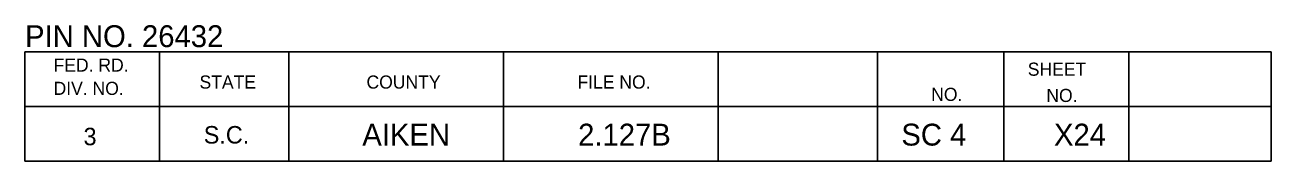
# Model space of a CAD drawing. Extents: x 1000 to 1162, y 999 to 8520.
# Drawn here: x 1133.06 to 1161.56, y 3745.05 to 3748.16 of the extents above; entities that cross this region are included whole.
import ezdxf

# ---------------------------------------------------------------- set-up
doc = ezdxf.new("R2010")
doc.units = 0
doc.layers.add('Level 20', color=7, linetype='Continuous')
doc.layers.add('Level 3', color=7, linetype='Continuous')

msp = doc.modelspace()

# ---------------------------------------------------------------- linework, layer by layer
at = {"layer": 'Level 3'}
for p, q in [((1133.055, 3747.546), (1161.555, 3747.546)), ((1133.055, 3747.546), (1133.055, 3745.046)), ((1133.055, 3747.546), (1161.555, 3747.546)), ((1133.055, 3747.546), (1133.055, 3745.046)), ((1133.055, 3747.546), (1161.555, 3747.546)), ((1133.055, 3747.546), (1133.055, 3745.046)), ((1133.055, 3747.546), (1161.555, 3747.546)), ((1133.055, 3747.546), (1133.055, 3745.046)), ((1133.055, 3747.546), (1161.555, 3747.546)), ((1133.055, 3747.546), (1133.055, 3745.046)), ((1133.055, 3747.546), (1161.555, 3747.546)), ((1133.055, 3747.546), (1133.055, 3745.046)), ((1133.055, 3747.546), (1161.555, 3747.546)), ((1133.055, 3747.546), (1133.055, 3745.046)), ((1133.055, 3747.546), (1161.555, 3747.546)), ((1133.055, 3747.546), (1133.055, 3745.046)), ((1133.055, 3747.546), (1161.555, 3747.546)), ((1133.055, 3747.546), (1133.055, 3745.046)), ((1133.055, 3747.546), (1161.555, 3747.546)), ((1133.055, 3747.546), (1133.055, 3745.046)), ((1133.055, 3747.546), (1161.555, 3747.546)), ((1133.055, 3747.546), (1133.055, 3745.046)), ((1133.055, 3747.546), (1161.555, 3747.546)), ((1133.055, 3747.546), (1133.055, 3745.046)), ((1133.055, 3747.546), (1161.555, 3747.546)), ((1133.055, 3747.546), (1133.055, 3745.046)), ((1133.055, 3747.546), (1161.555, 3747.546)), ((1133.055, 3747.546), (1133.055, 3745.046)), ((1133.055, 3747.546), (1161.555, 3747.546)), ((1133.055, 3747.546), (1133.055, 3745.046)), ((1133.055, 3747.546), (1161.555, 3747.546)), ((1133.055, 3747.546), (1133.055, 3745.046)), ((1133.055, 3747.546), (1161.555, 3747.546)), ((1133.055, 3747.546), (1133.055, 3745.046)), ((1133.055, 3747.546), (1161.555, 3747.546)), ((1133.055, 3747.546), (1133.055, 3745.046)), ((1133.055, 3747.546), (1161.555, 3747.546)), ((1133.055, 3747.546), (1133.055, 3745.046)), ((1133.055, 3747.546), (1161.555, 3747.546)), ((1133.055, 3747.546), (1133.055, 3745.046)), ((1133.055, 3747.546), (1161.555, 3747.546)), ((1133.055, 3747.546), (1133.055, 3745.046)), ((1133.055, 3747.546), (1161.555, 3747.546)), ((1133.055, 3747.546), (1133.055, 3745.046)), ((1136.132, 3747.546), (1136.132, 3745.046)), ((1136.132, 3747.546), (1136.132, 3745.046)), ((1136.132, 3747.546), (1136.132, 3745.046)), ((1136.132, 3747.546), (1136.132, 3745.046)), ((1136.132, 3747.546), (1136.132, 3745.046)), ((1136.132, 3747.546), (1136.132, 3745.046)), ((1136.132, 3747.546), (1136.132, 3745.046)), ((1136.132, 3747.546), (1136.132, 3745.046)), ((1136.132, 3747.546), (1136.132, 3745.046)), ((1136.132, 3747.546), (1136.132, 3745.046)), ((1136.132, 3747.546), (1136.132, 3745.046)), ((1136.132, 3747.546), (1136.132, 3745.046)), ((1136.132, 3747.546), (1136.132, 3745.046)), ((1136.132, 3747.546), (1136.132, 3745.046)), ((1136.132, 3747.546), (1136.132, 3745.046)), ((1136.132, 3747.546), (1136.132, 3745.046)), ((1136.132, 3747.546), (1136.132, 3745.046)), ((1136.132, 3747.546), (1136.132, 3745.046)), ((1136.132, 3747.546), (1136.132, 3745.046)), ((1136.132, 3747.546), (1136.132, 3745.046)), ((1136.132, 3747.546), (1136.132, 3745.046)), ((1136.132, 3747.546), (1136.132, 3745.046)), ((1139.087, 3747.546), (1139.087, 3745.046)), ((1139.087, 3747.546), (1139.087, 3745.046)), ((1139.087, 3747.546), (1139.087, 3745.046)), ((1139.087, 3747.546), (1139.087, 3745.046)), ((1139.087, 3747.546), (1139.087, 3745.046)), ((1139.087, 3747.546), (1139.087, 3745.046)), ((1139.087, 3747.546), (1139.087, 3745.046)), ((1139.087, 3747.546), (1139.087, 3745.046)), ((1139.087, 3747.546), (1139.087, 3745.046)), ((1139.087, 3747.546), (1139.087, 3745.046)), ((1139.087, 3747.546), (1139.087, 3745.046)), ((1139.087, 3747.546), (1139.087, 3745.046)), ((1139.087, 3747.546), (1139.087, 3745.046)), ((1139.087, 3747.546), (1139.087, 3745.046)), ((1139.087, 3747.546), (1139.087, 3745.046)), ((1139.087, 3747.546), (1139.087, 3745.046)), ((1139.087, 3747.546), (1139.087, 3745.046)), ((1139.087, 3747.546), (1139.087, 3745.046)), ((1139.087, 3747.546), (1139.087, 3745.046)), ((1139.087, 3747.546), (1139.087, 3745.046)), ((1139.087, 3747.546), (1139.087, 3745.046)), ((1139.087, 3747.546), (1139.087, 3745.046)), ((1144, 3747.546), (1144, 3745.046)), ((1144, 3747.546), (1144, 3745.046)), ((1144, 3747.546), (1144, 3745.046)), ((1144, 3747.546), (1144, 3745.046)), ((1144, 3747.546), (1144, 3745.046)), ((1144, 3747.546), (1144, 3745.046)), ((1144, 3747.546), (1144, 3745.046)), ((1144, 3747.546), (1144, 3745.046)), ((1144, 3747.546), (1144, 3745.046)), ((1144, 3747.546), (1144, 3745.046)), ((1144, 3747.546), (1144, 3745.046)), ((1144, 3747.546), (1144, 3745.046)), ((1144, 3747.546), (1144, 3745.046)), ((1144, 3747.546), (1144, 3745.046)), ((1144, 3747.546), (1144, 3745.046)), ((1144, 3747.546), (1144, 3745.046)), ((1144, 3747.546), (1144, 3745.046)), ((1144, 3747.546), (1144, 3745.046)), ((1144, 3747.546), (1144, 3745.046)), ((1144, 3747.546), (1144, 3745.046)), ((1144, 3747.546), (1144, 3745.046)), ((1144, 3747.546), (1144, 3745.046)), ((1148.913, 3747.546), (1148.913, 3745.046)), ((1148.913, 3747.546), (1148.913, 3745.046)), ((1148.913, 3747.546), (1148.913, 3745.046)), ((1148.913, 3747.546), (1148.913, 3745.046)), ((1148.913, 3747.546), (1148.913, 3745.046)), ((1148.913, 3747.546), (1148.913, 3745.046)), ((1148.913, 3747.546), (1148.913, 3745.046)), ((1148.913, 3747.546), (1148.913, 3745.046)), ((1148.913, 3747.546), (1148.913, 3745.046)), ((1148.913, 3747.546), (1148.913, 3745.046)), ((1148.913, 3747.546), (1148.913, 3745.046)), ((1148.913, 3747.546), (1148.913, 3745.046)), ((1148.913, 3747.546), (1148.913, 3745.046)), ((1148.913, 3747.546), (1148.913, 3745.046)), ((1148.913, 3747.546), (1148.913, 3745.046)), ((1148.913, 3747.546), (1148.913, 3745.046)), ((1148.913, 3747.546), (1148.913, 3745.046)), ((1148.913, 3747.546), (1148.913, 3745.046)), ((1148.913, 3747.546), (1148.913, 3745.046)), ((1148.913, 3747.546), (1148.913, 3745.046)), ((1148.913, 3747.546), (1148.913, 3745.046)), ((1148.913, 3747.546), (1148.913, 3745.046)), ((1152.554, 3747.546), (1152.554, 3745.046)), ((1152.554, 3747.546), (1152.554, 3745.046)), ((1152.554, 3747.546), (1152.554, 3745.046)), ((1152.554, 3747.546), (1152.554, 3745.046)), ((1152.554, 3747.546), (1152.554, 3745.046)), ((1152.554, 3747.546), (1152.554, 3745.046)), ((1152.554, 3747.546), (1152.554, 3745.046)), ((1152.554, 3747.546), (1152.554, 3745.046)), ((1152.554, 3747.546), (1152.554, 3745.046)), ((1152.554, 3747.546), (1152.554, 3745.046)), ((1152.554, 3747.546), (1152.554, 3745.046)), ((1152.554, 3747.546), (1152.554, 3745.046)), ((1152.554, 3747.546), (1152.554, 3745.046)), ((1152.554, 3747.546), (1152.554, 3745.046)), ((1152.554, 3747.546), (1152.554, 3745.046)), ((1152.554, 3747.546), (1152.554, 3745.046)), ((1152.554, 3747.546), (1152.554, 3745.046)), ((1152.554, 3747.546), (1152.554, 3745.046)), ((1152.554, 3747.546), (1152.554, 3745.046)), ((1152.554, 3747.546), (1152.554, 3745.046)), ((1152.554, 3747.546), (1152.554, 3745.046)), ((1152.554, 3747.546), (1152.554, 3745.046)), ((1155.44, 3747.546), (1155.44, 3745.046)), ((1155.44, 3747.546), (1155.44, 3745.046)), ((1155.44, 3747.546), (1155.44, 3745.046)), ((1155.44, 3747.546), (1155.44, 3745.046)), ((1155.44, 3747.546), (1155.44, 3745.046)), ((1155.44, 3747.546), (1155.44, 3745.046)), ((1155.44, 3747.546), (1155.44, 3745.046)), ((1155.44, 3747.546), (1155.44, 3745.046)), ((1155.44, 3747.546), (1155.44, 3745.046)), ((1155.44, 3747.546), (1155.44, 3745.046)), ((1155.44, 3747.546), (1155.44, 3745.046)), ((1155.44, 3747.546), (1155.44, 3745.046)), ((1155.44, 3747.546), (1155.44, 3745.046)), ((1155.44, 3747.546), (1155.44, 3745.046)), ((1155.44, 3747.546), (1155.44, 3745.046)), ((1155.44, 3747.546), (1155.44, 3745.046)), ((1155.44, 3747.546), (1155.44, 3745.046)), ((1155.44, 3747.546), (1155.44, 3745.046)), ((1155.44, 3747.546), (1155.44, 3745.046)), ((1155.44, 3747.546), (1155.44, 3745.046)), ((1155.44, 3747.546), (1155.44, 3745.046)), ((1155.44, 3747.546), (1155.44, 3745.046)), ((1158.305, 3747.546), (1158.305, 3745.046)), ((1158.305, 3747.546), (1158.305, 3745.046)), ((1158.305, 3747.546), (1158.305, 3745.046)), ((1158.305, 3747.546), (1158.305, 3745.046)), ((1158.305, 3747.546), (1158.305, 3745.046)), ((1158.305, 3747.546), (1158.305, 3745.046)), ((1158.305, 3747.546), (1158.305, 3745.046)), ((1158.305, 3747.546), (1158.305, 3745.046)), ((1158.305, 3747.546), (1158.305, 3745.046)), ((1158.305, 3747.546), (1158.305, 3745.046)), ((1158.305, 3747.546), (1158.305, 3745.046)), ((1158.305, 3747.546), (1158.305, 3745.046)), ((1158.305, 3747.546), (1158.305, 3745.046)), ((1158.305, 3747.546), (1158.305, 3745.046)), ((1158.305, 3747.546), (1158.305, 3745.046)), ((1158.305, 3747.546), (1158.305, 3745.046)), ((1158.305, 3747.546), (1158.305, 3745.046)), ((1158.305, 3747.546), (1158.305, 3745.046)), ((1158.305, 3747.546), (1158.305, 3745.046)), ((1158.305, 3747.546), (1158.305, 3745.046)), ((1158.305, 3747.546), (1158.305, 3745.046)), ((1158.305, 3747.546), (1158.305, 3745.046)), ((1161.555, 3747.546), (1161.555, 3745.046)), ((1161.555, 3747.546), (1161.555, 3745.046)), ((1161.555, 3747.546), (1161.555, 3745.046)), ((1161.555, 3747.546), (1161.555, 3745.046)), ((1161.555, 3747.546), (1161.555, 3745.046)), ((1161.555, 3747.546), (1161.555, 3745.046)), ((1161.555, 3747.546), (1161.555, 3745.046)), ((1161.555, 3747.546), (1161.555, 3745.046)), ((1161.555, 3747.546), (1161.555, 3745.046)), ((1161.555, 3747.546), (1161.555, 3745.046)), ((1161.555, 3747.546), (1161.555, 3745.046)), ((1161.555, 3747.546), (1161.555, 3745.046)), ((1161.555, 3747.546), (1161.555, 3745.046)), ((1161.555, 3747.546), (1161.555, 3745.046)), ((1161.555, 3747.546), (1161.555, 3745.046)), ((1161.555, 3747.546), (1161.555, 3745.046)), ((1161.555, 3747.546), (1161.555, 3745.046)), ((1161.555, 3747.546), (1161.555, 3745.046)), ((1161.555, 3747.546), (1161.555, 3745.046)), ((1161.555, 3747.546), (1161.555, 3745.046)), ((1161.555, 3747.546), (1161.555, 3745.046)), ((1161.555, 3747.546), (1161.555, 3745.046)), ((1133.055, 3746.296), (1161.555, 3746.296)), ((1133.055, 3746.296), (1161.555, 3746.296)), ((1133.055, 3746.296), (1161.555, 3746.296)), ((1133.055, 3746.296), (1161.555, 3746.296)), ((1133.055, 3746.296), (1161.555, 3746.296)), ((1133.055, 3746.296), (1161.555, 3746.296)), ((1133.055, 3746.296), (1161.555, 3746.296)), ((1133.055, 3746.296), (1161.555, 3746.296)), ((1133.055, 3746.296), (1161.555, 3746.296)), ((1133.055, 3746.296), (1161.555, 3746.296)), ((1133.055, 3746.296), (1161.555, 3746.296)), ((1133.055, 3746.296), (1161.555, 3746.296)), ((1133.055, 3746.296), (1161.555, 3746.296)), ((1133.055, 3746.296), (1161.555, 3746.296)), ((1133.055, 3746.296), (1161.555, 3746.296)), ((1133.055, 3746.296), (1161.555, 3746.296)), ((1133.055, 3746.296), (1161.555, 3746.296)), ((1133.055, 3746.296), (1161.555, 3746.296)), ((1133.055, 3746.296), (1161.555, 3746.296)), ((1133.055, 3746.296), (1161.555, 3746.296)), ((1133.055, 3746.296), (1161.555, 3746.296)), ((1133.055, 3746.296), (1161.555, 3746.296)), ((1133.055, 3745.046), (1161.555, 3745.046)), ((1133.055, 3745.046), (1161.555, 3745.046)), ((1133.055, 3745.046), (1161.555, 3745.046)), ((1133.055, 3745.046), (1161.555, 3745.046)), ((1133.055, 3745.046), (1161.555, 3745.046)), ((1133.055, 3745.046), (1161.555, 3745.046)), ((1133.055, 3745.046), (1161.555, 3745.046)), ((1133.055, 3745.046), (1161.555, 3745.046)), ((1133.055, 3745.046), (1161.555, 3745.046)), ((1133.055, 3745.046), (1161.555, 3745.046)), ((1133.055, 3745.046), (1161.555, 3745.046)), ((1133.055, 3745.046), (1161.555, 3745.046)), ((1133.055, 3745.046), (1161.555, 3745.046)), ((1133.055, 3745.046), (1161.555, 3745.046)), ((1133.055, 3745.046), (1161.555, 3745.046)), ((1133.055, 3745.046), (1161.555, 3745.046)), ((1133.055, 3745.046), (1161.555, 3745.046)), ((1133.055, 3745.046), (1161.555, 3745.046)), ((1133.055, 3745.046), (1161.555, 3745.046)), ((1133.055, 3745.046), (1161.555, 3745.046)), ((1133.055, 3745.046), (1161.555, 3745.046)), ((1133.055, 3745.046), (1161.555, 3745.046))]:
    msp.add_line(p, q, dxfattribs=at)

# ---------------------------------------------------------------- texts
at = {"layer": 'Level 20'}
for s, p in [('PIN NO. 26432', (1133.058, 3747.65)), ('AIKEN', (1140.771, 3745.4)), ('2.127B', (1145.707, 3745.4)), ('SC 4', (1153.099, 3745.4)), ('X24', (1156.59, 3745.4))]:
    msp.add_text(s, height=0.5, dxfattribs=at).set_placement(p)
at = {"layer": 'Level 3'}
for s, height, p in [('FED. RD.', 0.3, (1133.71, 3747.09)), ('FED. RD.', 0.3, (1133.71, 3747.09)), ('FED. RD.', 0.3, (1133.71, 3747.09)), ('FED. RD.', 0.3, (1133.71, 3747.09)), ('FED. RD.', 0.3, (1133.71, 3747.09)), ('FED. RD.', 0.3, (1133.71, 3747.09)), ('FED. RD.', 0.3, (1133.71, 3747.09)), ('FED. RD.', 0.3, (1133.71, 3747.09)), ('FED. RD.', 0.3, (1133.71, 3747.09)), ('FED. RD.', 0.3, (1133.71, 3747.09)), ('FED. RD.', 0.3, (1133.71, 3747.09)), ('FED. RD.', 0.3, (1133.71, 3747.09)), ('FED. RD.', 0.3, (1133.71, 3747.09)), ('FED. RD.', 0.3, (1133.71, 3747.09)), ('FED. RD.', 0.3, (1133.71, 3747.09)), ('FED. RD.', 0.3, (1133.71, 3747.09)), ('FED. RD.', 0.3, (1133.71, 3747.09)), ('FED. RD.', 0.3, (1133.71, 3747.09)), ('FED. RD.', 0.3, (1133.71, 3747.09)), ('FED. RD.', 0.3, (1133.71, 3747.09)), ('FED. RD.', 0.3, (1133.71, 3747.09)), ('FED. RD.', 0.3, (1133.71, 3747.09)), ('SHEET', 0.3, (1155.99, 3746.996)), ('SHEET', 0.3, (1155.99, 3746.996)), ('SHEET', 0.3, (1155.99, 3746.996)), ('SHEET', 0.3, (1155.99, 3746.996)), ('SHEET', 0.3, (1155.99, 3746.996)), ('SHEET', 0.3, (1155.99, 3746.996)), ('SHEET', 0.3, (1155.99, 3746.996)), ('SHEET', 0.3, (1155.99, 3746.996)), ('SHEET', 0.3, (1155.99, 3746.996)), ('SHEET', 0.3, (1155.99, 3746.996)), ('SHEET', 0.3, (1155.99, 3746.996)), ('SHEET', 0.3, (1155.99, 3746.996)), ('SHEET', 0.3, (1155.99, 3746.996)), ('SHEET', 0.3, (1155.99, 3746.996)), ('SHEET', 0.3, (1155.99, 3746.996)), ('SHEET', 0.3, (1155.99, 3746.996)), ('SHEET', 0.3, (1155.99, 3746.996)), ('SHEET', 0.3, (1155.99, 3746.996)), ('SHEET', 0.3, (1155.99, 3746.996)), ('SHEET', 0.3, (1155.99, 3746.996)), ('SHEET', 0.3, (1155.99, 3746.996)), ('SHEET', 0.3, (1155.99, 3746.996)), ('STATE', 0.3, (1137.048, 3746.702)), ('STATE', 0.3, (1137.048, 3746.702)), ('STATE', 0.3, (1137.048, 3746.702)), ('STATE', 0.3, (1137.048, 3746.702)), ('STATE', 0.3, (1137.048, 3746.702)), ('STATE', 0.3, (1137.048, 3746.702)), ('STATE', 0.3, (1137.048, 3746.702)), ('STATE', 0.3, (1137.048, 3746.702)), ('STATE', 0.3, (1137.048, 3746.702)), ('STATE', 0.3, (1137.048, 3746.702)), ('STATE', 0.3, (1137.048, 3746.702)), ('STATE', 0.3, (1137.048, 3746.702)), ('STATE', 0.3, (1137.048, 3746.702)), ('STATE', 0.3, (1137.048, 3746.702)), ('STATE', 0.3, (1137.048, 3746.702)), ('STATE', 0.3, (1137.048, 3746.702)), ('STATE', 0.3, (1137.048, 3746.702)), ('STATE', 0.3, (1137.048, 3746.702)), ('STATE', 0.3, (1137.048, 3746.702)), ('STATE', 0.3, (1137.048, 3746.702)), ('STATE', 0.3, (1137.048, 3746.702)), ('STATE', 0.3, (1137.048, 3746.702)), ('COUNTY', 0.3, (1140.867, 3746.702)), ('COUNTY', 0.3, (1140.867, 3746.702)), ('COUNTY', 0.3, (1140.867, 3746.702)), ('COUNTY', 0.3, (1140.867, 3746.702)), ('COUNTY', 0.3, (1140.867, 3746.702)), ('COUNTY', 0.3, (1140.867, 3746.702)), ('COUNTY', 0.3, (1140.867, 3746.702)), ('COUNTY', 0.3, (1140.867, 3746.702)), ('COUNTY', 0.3, (1140.867, 3746.702)), ('COUNTY', 0.3, (1140.867, 3746.702)), ('COUNTY', 0.3, (1140.867, 3746.702)), ('COUNTY', 0.3, (1140.867, 3746.702)), ('COUNTY', 0.3, (1140.867, 3746.702)), ('COUNTY', 0.3, (1140.867, 3746.702)), ('COUNTY', 0.3, (1140.867, 3746.702)), ('COUNTY', 0.3, (1140.867, 3746.702)), ('COUNTY', 0.3, (1140.867, 3746.702)), ('COUNTY', 0.3, (1140.867, 3746.702)), ('COUNTY', 0.3, (1140.867, 3746.702)), ('COUNTY', 0.3, (1140.867, 3746.702)), ('COUNTY', 0.3, (1140.867, 3746.702)), ('COUNTY', 0.3, (1140.867, 3746.702)), ('FILE NO.', 0.3, (1145.691, 3746.702)), ('FILE NO.', 0.3, (1145.691, 3746.702)), ('FILE NO.', 0.3, (1145.691, 3746.702)), ('FILE NO.', 0.3, (1145.691, 3746.702)), ('FILE NO.', 0.3, (1145.691, 3746.702)), ('FILE NO.', 0.3, (1145.691, 3746.702)), ('FILE NO.', 0.3, (1145.691, 3746.702)), ('FILE NO.', 0.3, (1145.691, 3746.702)), ('FILE NO.', 0.3, (1145.691, 3746.702)), ('FILE NO.', 0.3, (1145.691, 3746.702)), ('FILE NO.', 0.3, (1145.691, 3746.702)), ('FILE NO.', 0.3, (1145.691, 3746.702)), ('FILE NO.', 0.3, (1145.691, 3746.702)), ('FILE NO.', 0.3, (1145.691, 3746.702)), ('FILE NO.', 0.3, (1145.691, 3746.702)), ('FILE NO.', 0.3, (1145.691, 3746.702)), ('FILE NO.', 0.3, (1145.691, 3746.702)), ('FILE NO.', 0.3, (1145.691, 3746.702)), ('FILE NO.', 0.3, (1145.691, 3746.702)), ('FILE NO.', 0.3, (1145.691, 3746.702)), ('FILE NO.', 0.3, (1145.691, 3746.702)), ('FILE NO.', 0.3, (1145.691, 3746.702)), ('DIV. NO.', 0.3, (1133.71, 3746.558)), ('DIV. NO.', 0.3, (1133.71, 3746.558)), ('DIV. NO.', 0.3, (1133.71, 3746.558)), ('DIV. NO.', 0.3, (1133.71, 3746.558)), ('DIV. NO.', 0.3, (1133.71, 3746.558)), ('DIV. NO.', 0.3, (1133.71, 3746.558)), ('DIV. NO.', 0.3, (1133.71, 3746.558)), ('DIV. NO.', 0.3, (1133.71, 3746.558)), ('DIV. NO.', 0.3, (1133.71, 3746.558)), ('DIV. NO.', 0.3, (1133.71, 3746.558)), ('DIV. NO.', 0.3, (1133.71, 3746.558)), ('DIV. NO.', 0.3, (1133.71, 3746.558)), ('DIV. NO.', 0.3, (1133.71, 3746.558)), ('DIV. NO.', 0.3, (1133.71, 3746.558)), ('DIV. NO.', 0.3, (1133.71, 3746.558)), ('DIV. NO.', 0.3, (1133.71, 3746.558)), ('DIV. NO.', 0.3, (1133.71, 3746.558)), ('DIV. NO.', 0.3, (1133.71, 3746.558)), ('DIV. NO.', 0.3, (1133.71, 3746.558)), ('DIV. NO.', 0.3, (1133.71, 3746.558)), ('DIV. NO.', 0.3, (1133.71, 3746.558)), ('DIV. NO.', 0.3, (1133.71, 3746.558)), ('NO.', 0.3, (1153.782, 3746.421)), ('NO.', 0.3, (1153.782, 3746.421)), ('NO.', 0.3, (1153.782, 3746.421)), ('NO.', 0.3, (1153.782, 3746.421)), ('NO.', 0.3, (1153.782, 3746.421)), ('NO.', 0.3, (1153.782, 3746.421)), ('NO.', 0.3, (1153.782, 3746.421)), ('NO.', 0.3, (1153.782, 3746.421)), ('NO.', 0.3, (1153.782, 3746.421)), ('NO.', 0.3, (1153.782, 3746.421)), ('NO.', 0.3, (1153.782, 3746.421)), ('NO.', 0.3, (1153.782, 3746.421)), ('NO.', 0.3, (1153.782, 3746.421)), ('NO.', 0.3, (1153.782, 3746.421)), ('NO.', 0.3, (1153.782, 3746.421)), ('NO.', 0.3, (1153.782, 3746.421)), ('NO.', 0.3, (1153.782, 3746.421)), ('NO.', 0.3, (1153.782, 3746.421)), ('NO.', 0.3, (1153.782, 3746.421)), ('NO.', 0.3, (1153.782, 3746.421)), ('NO.', 0.3, (1153.782, 3746.421)), ('NO.', 0.3, (1153.782, 3746.421)), ('NO.', 0.3, (1156.415, 3746.396)), ('NO.', 0.3, (1156.415, 3746.396)), ('NO.', 0.3, (1156.415, 3746.396)), ('NO.', 0.3, (1156.415, 3746.396)), ('NO.', 0.3, (1156.415, 3746.396)), ('NO.', 0.3, (1156.415, 3746.396)), ('NO.', 0.3, (1156.415, 3746.396)), ('NO.', 0.3, (1156.415, 3746.396)), ('NO.', 0.3, (1156.415, 3746.396)), ('NO.', 0.3, (1156.415, 3746.396)), ('NO.', 0.3, (1156.415, 3746.396)), ('NO.', 0.3, (1156.415, 3746.396)), ('NO.', 0.3, (1156.415, 3746.396)), ('NO.', 0.3, (1156.415, 3746.396)), ('NO.', 0.3, (1156.415, 3746.396)), ('NO.', 0.3, (1156.415, 3746.396)), ('NO.', 0.3, (1156.415, 3746.396)), ('NO.', 0.3, (1156.415, 3746.396)), ('NO.', 0.3, (1156.415, 3746.396)), ('NO.', 0.3, (1156.415, 3746.396)), ('NO.', 0.3, (1156.415, 3746.396)), ('NO.', 0.3, (1156.415, 3746.396)), ('3', 0.4, (1134.396, 3745.407)), ('3', 0.4, (1134.396, 3745.407)), ('3', 0.4, (1134.396, 3745.407)), ('3', 0.4, (1134.396, 3745.407)), ('3', 0.4, (1134.396, 3745.407)), ('3', 0.4, (1134.396, 3745.407)), ('3', 0.4, (1134.396, 3745.407)), ('3', 0.4, (1134.396, 3745.407)), ('3', 0.4, (1134.396, 3745.407)), ('3', 0.4, (1134.396, 3745.407)), ('3', 0.4, (1134.396, 3745.407)), ('3', 0.4, (1134.396, 3745.407)), ('3', 0.4, (1134.396, 3745.407)), ('3', 0.4, (1134.396, 3745.407)), ('3', 0.4, (1134.396, 3745.407)), ('3', 0.4, (1134.396, 3745.407)), ('3', 0.4, (1134.396, 3745.407)), ('3', 0.4, (1134.396, 3745.407)), ('3', 0.4, (1134.396, 3745.407)), ('3', 0.4, (1134.396, 3745.407)), ('3', 0.4, (1134.396, 3745.407)), ('3', 0.4, (1134.396, 3745.407)), ('S.C.', 0.4, (1137.145, 3745.446)), ('S.C.', 0.4, (1137.145, 3745.446)), ('S.C.', 0.4, (1137.145, 3745.446)), ('S.C.', 0.4, (1137.145, 3745.446)), ('S.C.', 0.4, (1137.145, 3745.446)), ('S.C.', 0.4, (1137.145, 3745.446)), ('S.C.', 0.4, (1137.145, 3745.446)), ('S.C.', 0.4, (1137.145, 3745.446)), ('S.C.', 0.4, (1137.145, 3745.446)), ('S.C.', 0.4, (1137.145, 3745.446)), ('S.C.', 0.4, (1137.145, 3745.446)), ('S.C.', 0.4, (1137.145, 3745.446)), ('S.C.', 0.4, (1137.145, 3745.446)), ('S.C.', 0.4, (1137.145, 3745.446)), ('S.C.', 0.4, (1137.145, 3745.446)), ('S.C.', 0.4, (1137.145, 3745.446)), ('S.C.', 0.4, (1137.145, 3745.446)), ('S.C.', 0.4, (1137.145, 3745.446)), ('S.C.', 0.4, (1137.145, 3745.446)), ('S.C.', 0.4, (1137.145, 3745.446)), ('S.C.', 0.4, (1137.145, 3745.446)), ('S.C.', 0.4, (1137.145, 3745.446))]:
    msp.add_text(s, height=height, dxfattribs=at).set_placement(p)

doc.saveas('drawing.dxf')
